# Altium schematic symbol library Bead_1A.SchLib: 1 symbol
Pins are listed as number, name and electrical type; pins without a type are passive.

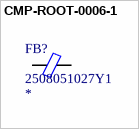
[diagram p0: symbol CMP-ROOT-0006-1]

## CMP-ROOT-0006-1
designator FB?, comment 2508051027Y1
FERRITE BEAD 0805 1LN; Value: 0805; Value: 1.25mm; Value: -55°C; Value: SMD/SMT; Value: 1A; Value: Fair-Rite; Value: 03038048; Value: 125°C; Value: 100MHz; Value: 1kR; Value: SMD; Value: FERRITE BEAD 0805 - P/N: 2508051027Y1; Value: Tape and Reel; Value: 4000; Value: 300mR; Value: 2mm; Value: 25%; Value: 0.9mm
footprint Ferrite 0805
pins: 1, 2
